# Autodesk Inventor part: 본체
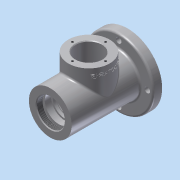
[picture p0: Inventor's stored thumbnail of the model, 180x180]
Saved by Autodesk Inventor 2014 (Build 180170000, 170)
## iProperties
Created: 2016-08
Part Number: 본체
Material: 알루미늄 6061
Document SubType Name: Modeling
Designer: 703-04
Density: 2.71 g/cm^3
Appearance: 알루미늄 - 평지
Author: 703-04
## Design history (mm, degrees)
sketch "스케치2"
  geometry: C1 r 31 at (0, 0); 1 further point
  constraints: 1 centre point, 1 coincident
  dimensions: "d0" = 62 diameter of C1
extrude "돌출1" new body sketch "스케치2" distance "d1" = 56; taper "d3" = 0 deg; dims "d2" = 59, "d4" = 0
node "작업 평면1"
sketch "스케치3"
  geometry: C1 r 50 at (0, 0); 1 further point
  constraints: 1 centre point, 1 coincident
  dimensions: "d6" = 100 diameter of C1
extrude "돌출2" join sketch "스케치3" distance "d7" = 13; taper "d8" = 0 deg
node "작업 평면2"
sketch "스케치4"
  geometry: C1 r 30 at (0, 0); 1 further point
  constraints: 1 centre point, 1 coincident
  dimensions: "d10" = 60 diameter of C1
extrude "돌출3" join sketch "스케치4" stored distance "d11" = 13; taper "d12" = 0 deg
node "작업 평면3"
sketch "스케치5"
  geometry: C1 r 26 at (0, -1.89); 1 further point
  constraints: 1 centre point
  dimensions: "d14" = 52 diameter of C1
extrude "돌출4" cut sketch "스케치5" stored distance "d15" = 38; taper "d16" = 0 deg
hole "구멍1" diameter "d19" = 40.376; stored, may be unused: countersink angle "d23" = 90 deg, drill point angle "d25" = 0 deg; dims "d17" = 10, "d18" = 10, "d20" = 6, "d21" = 4, "d22" = 2, "d24" = 9
node "작업 평면4"
node "작업 평면5"
sketch "스케치6"
  geometry: C1 r 24 at (0, 0); 1 further point
  constraints: 1 centre point, 1 coincident
  dimensions: "d27" = 48 diameter of C1
extrude "돌출5" cut sketch "스케치6" distance "d28" = 3; taper "d29" = 0 deg
hole "구멍2" diameter "d32" = 40; stored, may be unused: countersink angle "d36" = 90 deg, drill point angle "d38" = 0 deg; dims "d33" = 6, "d34" = 4, "d35" = 2, "d37" = 9, "d70" = 10, "d71" = 10
hole "구멍3" diameter "d41" = 35; stored, may be unused: countersink angle "d45" = 90 deg, drill point angle "d47" = 0 deg; dims "d39" = 10, "d40" = 10, "d42" = 6, "d43" = 4, "d44" = 2, "d46" = 3.25
hole "구멍4" diameter "d50" = 37; stored, may be unused: countersink angle "d54" = 90 deg, drill point angle "d56" = 0 deg; dims "d48" = 10, "d49" = 10, "d51" = 6, "d52" = 4, "d53" = 2, "d55" = 1.75
sketch "스케치7"
  geometry: L1 (-31, -59)-(31, -59) reference; L2 (21, -59)-(16, -45); L3 (0, -70.8)-(0, 11.8) reference; L4 (16, -45)-(12.5, -45); L5 (12.5, -45)-(12.5, -37.7); L6 (12.5, -37.7)-(10, -37.7); L7 (10, -37.7)-(10, -35); L8 (10, -35)-(0, -35); L9 (21, -59)-(0, -59); L10 (0, -59)-(0, -35); 1 further point
  constraints: 16 end point, 3 perpendicular, 3 point on line, 2 parallel, 1 collinear, 1 midpoint
  dimensions: "d57" = 42 diameter of L2.start L3; "d58" = 32 diameter of L2.end L3; "d59" = 14 vertical distance of L2.start L2.end; "d60" = 25 diameter of L5 L3; "d61" = 7.3 distance of L4.end L5.end; "d62" = 20 diameter of L7 L3; "d63" = 2.7 distance of L6.end L7.end
revolve "회전1" sketch "스케치7" stored, may be unused: angle "d64" = 90 deg
sketch "스케치8"
  geometry: C1 r 17.5 at (0, 0); 1 further point
  constraints: 1 centre point, 1 coincident
  dimensions: "d65" = 35 diameter of C1
extrude "돌출6" cut sketch "스케치8" stored distance "d66" = 60; taper "d67" = 0 deg
hole "구멍5" diameter "d72" = 33; stored, may be unused: countersink angle "d76" = 90 deg, drill point angle "d78" = 0 deg; dims "d68" = 10, "d69" = 10, "d73" = 6, "d74" = 4, "d75" = 2, "d77" = 5
fillet "모깎기1" dims "d79" = 3
fillet "모깎기2" dims "d80" = 0.3
chamfer "모따기2" distance "d84" = 0.7; stored, may be unused: second distance "d85" = 2, angle "d86" = 60 deg
hole "구멍6" diameter "d89" = 38; stored, may be unused: countersink angle "d93" = 90 deg, drill point angle "d95" = 0 deg; dims "d87" = 10, "d88" = 10, "d90" = 6, "d91" = 4, "d92" = 2, "d94" = 50
sketch "스케치9"
  geometry: C1 r 19 at (0, 0) reference; 1 further point
  constraints: 1 vertical alignment
  dimensions: "d96" = 24 distance of point (0, 24) C1.centre
hole "구멍7" sketch "스케치9" at (0, 24) diameter "d97" = 3.242; stored, may be unused: countersink angle "d101" = 90 deg, drill point angle "d103" = 118 deg; dims "d98" = 8, "d99" = 4, "d100" = 2, "d102" = 10
chamfer "모따기3" distance "d107" = 1; stored, may be unused: second distance "d108" = 2, angle "d109" = 60 deg
fillet "모깎기3" dims "d110" = 3
sketch "스케치10"
  geometry: C1 r 50 at (0, 0) reference; 1 further point
  constraints: 1 vertical alignment
  dimensions: "d111" = 41.5 distance of point (0, 41.5) C1.centre
hole "구멍8" sketch "스케치10" at (0, 41.5) diameter "d112" = 8; stored, may be unused: countersink angle "d116" = 90 deg, drill point angle "d118" = 0 deg; dims "d113" = 8, "d114" = 4, "d115" = 2, "d117" = 20
node "작업 평면6"
sketch "스케치11"
  geometry: L1 (31, 56)-(-31, 56) reference; L2 (49, 30)-(49, -30) reference; 2 further points
  constraints: 1 other
  dimensions: "d123" = 56 distance from line of point (39, 0) L1; "d124" = 10 distance from line of point (39, 0) L2
feature "엠보싱1" sketch "스케치11" dims "d0" = 62, "d15" = 38, "d125" = 0.5, "d126" = 0
chamfer "모따기4" distance "d127" = 1; stored, may be unused: second distance "d128" = 2, angle "d129" = 45 deg
chamfer "모따기5" distance "d130" = 1; stored, may be unused: second distance "d131" = 2, angle "d132" = 45 deg
chamfer "모따기6" distance "d133" = 1; stored, may be unused: second distance "d134" = 2, angle "d135" = 45 deg
node "솔리드1"
pattern_circular "원형 패턴1" dims angle "d105" = 360 deg
pattern_circular "원형 패턴2" dims angle "d120" = 360 deg
other parameters: "d5" = -3, "d9" = 49, "d13" = -56, "d26" = -9
